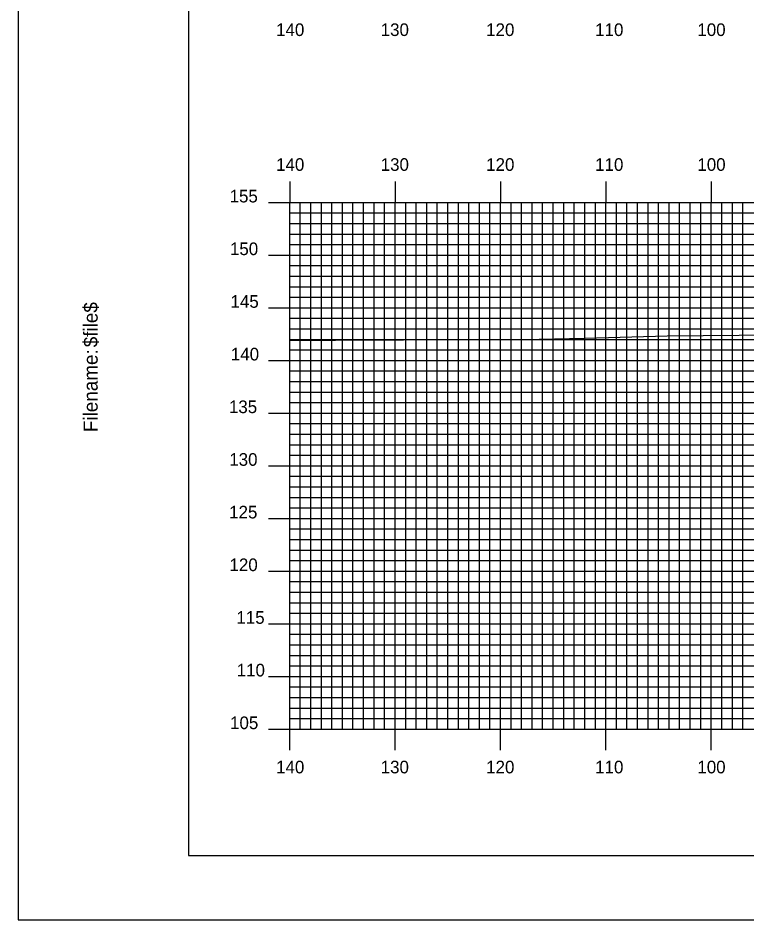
# Model space of a CAD drawing. Extents: x 1769268 to 1769611, y 442591 to 442811.
# Drawn here: x 1769267.7 to 1769336.9, y 442590.5 to 442676.2 of the extents above; entities that cross this region are included whole.
import ezdxf

# ---------------------------------------------------------------- set-up
doc = ezdxf.new("R2010")
doc.units = 0
for name, color, linetype in [('BORDER', 7, 'Continuous'), ('H_V ANNOTATION', 7, 'Continuous'), ('MAJOR', 7, 'Continuous'), ('MINOR', 7, 'Continuous'), ('PLOT BOUNDARY', 7, 'Continuous'), ('S_Roadway_Centerline', 7, 'Continuous')]:
    doc.layers.add(name, color=color, linetype=linetype)

msp = doc.modelspace()

# ---------------------------------------------------------------- linework, layer by layer
at = {"layer": 'BORDER'}
msp.add_lwpolyline([(1769283.902, 442596.665), (1769603.902, 442596.665), (1769603.902, 442806.665), (1769283.902, 442806.665)], close=True, dxfattribs=at)
at = {"layer": 'MAJOR'}
for p, q in [((1769293.502, 442660.669), (1769293.502, 442658.665)), ((1769303.502, 442660.669), (1769303.502, 442658.665)), ((1769313.502, 442660.669), (1769313.502, 442658.665)), ((1769323.502, 442660.669), (1769323.502, 442658.665)), ((1769333.502, 442660.669), (1769333.502, 442658.665)), ((1769291.498, 442658.665), (1769293.502, 442658.665)), ((1769293.502, 442658.665), (1769573.502, 442658.665)), ((1769293.502, 442608.665), (1769293.502, 442658.665)), ((1769293.502, 442608.665), (1769293.502, 442658.665)), ((1769293.502, 442658.665), (1769573.502, 442658.665)), ((1769303.502, 442608.665), (1769303.502, 442658.665)), ((1769313.502, 442608.665), (1769313.502, 442658.665)), ((1769323.502, 442608.665), (1769323.502, 442658.665)), ((1769333.502, 442608.665), (1769333.502, 442658.665)), ((1769291.498, 442653.665), (1769293.502, 442653.665)), ((1769293.502, 442653.665), (1769573.502, 442653.665)), ((1769291.498, 442648.665), (1769293.502, 442648.665)), ((1769293.502, 442648.665), (1769573.502, 442648.665)), ((1769291.498, 442643.665), (1769293.502, 442643.665)), ((1769293.502, 442643.665), (1769573.502, 442643.665)), ((1769291.498, 442638.665), (1769293.502, 442638.665)), ((1769293.502, 442638.665), (1769573.502, 442638.665)), ((1769291.498, 442633.665), (1769293.502, 442633.665)), ((1769293.502, 442633.665), (1769573.502, 442633.665)), ((1769291.498, 442628.665), (1769293.502, 442628.665)), ((1769293.502, 442628.665), (1769573.502, 442628.665)), ((1769291.498, 442623.665), (1769293.502, 442623.665)), ((1769293.502, 442623.665), (1769573.502, 442623.665)), ((1769291.498, 442618.665), (1769293.502, 442618.665)), ((1769293.502, 442618.665), (1769573.502, 442618.665)), ((1769291.498, 442613.665), (1769293.502, 442613.665)), ((1769293.502, 442613.665), (1769573.502, 442613.665)), ((1769291.498, 442608.665), (1769293.502, 442608.665)), ((1769293.502, 442608.665), (1769573.502, 442608.665)), ((1769293.502, 442608.665), (1769573.502, 442608.665)), ((1769293.502, 442606.661), (1769293.502, 442608.665)), ((1769303.502, 442606.661), (1769303.502, 442608.665)), ((1769313.502, 442606.661), (1769313.502, 442608.665)), ((1769323.502, 442606.661), (1769323.502, 442608.665)), ((1769333.502, 442606.661), (1769333.502, 442608.665))]:
    msp.add_line(p, q, dxfattribs=at)
at = {"layer": 'MINOR'}
for p, q in [((1769294.502, 442608.665), (1769294.502, 442658.665)), ((1769295.502, 442608.665), (1769295.502, 442658.665)), ((1769296.502, 442608.665), (1769296.502, 442658.665)), ((1769297.502, 442608.665), (1769297.502, 442658.665)), ((1769298.502, 442608.665), (1769298.502, 442658.665)), ((1769299.502, 442608.665), (1769299.502, 442658.665)), ((1769300.502, 442608.665), (1769300.502, 442658.665)), ((1769301.502, 442608.665), (1769301.502, 442658.665)), ((1769302.502, 442608.665), (1769302.502, 442658.665)), ((1769304.502, 442608.665), (1769304.502, 442658.665)), ((1769305.502, 442608.665), (1769305.502, 442658.665)), ((1769306.502, 442608.665), (1769306.502, 442658.665)), ((1769307.502, 442608.665), (1769307.502, 442658.665)), ((1769308.502, 442608.665), (1769308.502, 442658.665)), ((1769309.502, 442608.665), (1769309.502, 442658.665)), ((1769310.502, 442608.665), (1769310.502, 442658.665)), ((1769311.502, 442608.665), (1769311.502, 442658.665)), ((1769312.502, 442608.665), (1769312.502, 442658.665)), ((1769314.502, 442608.665), (1769314.502, 442658.665)), ((1769315.502, 442608.665), (1769315.502, 442658.665)), ((1769316.502, 442608.665), (1769316.502, 442658.665)), ((1769317.502, 442608.665), (1769317.502, 442658.665)), ((1769318.502, 442608.665), (1769318.502, 442658.665)), ((1769319.502, 442608.665), (1769319.502, 442658.665)), ((1769320.502, 442608.665), (1769320.502, 442658.665)), ((1769321.502, 442608.665), (1769321.502, 442658.665)), ((1769322.502, 442608.665), (1769322.502, 442658.665)), ((1769324.502, 442608.665), (1769324.502, 442658.665)), ((1769325.502, 442608.665), (1769325.502, 442658.665)), ((1769326.502, 442608.665), (1769326.502, 442658.665)), ((1769327.502, 442608.665), (1769327.502, 442658.665)), ((1769328.502, 442608.665), (1769328.502, 442658.665)), ((1769329.502, 442608.665), (1769329.502, 442658.665)), ((1769330.502, 442608.665), (1769330.502, 442658.665)), ((1769331.502, 442608.665), (1769331.502, 442658.665)), ((1769332.502, 442608.665), (1769332.502, 442658.665)), ((1769334.502, 442608.665), (1769334.502, 442658.665)), ((1769335.502, 442608.665), (1769335.502, 442658.665)), ((1769336.502, 442608.665), (1769336.502, 442658.665)), ((1769293.502, 442657.665), (1769573.502, 442657.665)), ((1769293.502, 442657.665), (1769295.506, 442657.665)), ((1769293.502, 442656.665), (1769573.502, 442656.665)), ((1769293.502, 442656.665), (1769295.506, 442656.665)), ((1769293.502, 442655.665), (1769573.502, 442655.665)), ((1769293.502, 442655.665), (1769295.506, 442655.665)), ((1769293.502, 442654.665), (1769573.502, 442654.665)), ((1769293.502, 442654.665), (1769295.506, 442654.665)), ((1769293.502, 442652.665), (1769573.502, 442652.665)), ((1769293.502, 442652.665), (1769295.506, 442652.665)), ((1769293.502, 442651.665), (1769573.502, 442651.665)), ((1769293.502, 442651.665), (1769295.506, 442651.665)), ((1769293.502, 442650.665), (1769573.502, 442650.665)), ((1769293.502, 442650.665), (1769295.506, 442650.665)), ((1769293.502, 442649.665), (1769573.502, 442649.665)), ((1769293.502, 442649.665), (1769295.506, 442649.665)), ((1769293.502, 442647.665), (1769573.502, 442647.665)), ((1769293.502, 442647.665), (1769295.506, 442647.665)), ((1769293.502, 442646.665), (1769573.502, 442646.665)), ((1769293.502, 442646.665), (1769295.506, 442646.665)), ((1769293.502, 442645.665), (1769573.502, 442645.665)), ((1769293.502, 442645.665), (1769295.506, 442645.665)), ((1769293.502, 442644.665), (1769573.502, 442644.665)), ((1769293.502, 442644.665), (1769295.506, 442644.665)), ((1769293.502, 442642.665), (1769573.502, 442642.665)), ((1769293.502, 442642.665), (1769295.506, 442642.665)), ((1769293.502, 442641.665), (1769573.502, 442641.665)), ((1769293.502, 442641.665), (1769295.506, 442641.665)), ((1769293.502, 442640.665), (1769573.502, 442640.665)), ((1769293.502, 442640.665), (1769295.506, 442640.665)), ((1769293.502, 442639.665), (1769573.502, 442639.665)), ((1769293.502, 442639.665), (1769295.506, 442639.665)), ((1769293.502, 442637.665), (1769573.502, 442637.665)), ((1769293.502, 442637.665), (1769295.506, 442637.665)), ((1769293.502, 442636.665), (1769573.502, 442636.665)), ((1769293.502, 442636.665), (1769295.506, 442636.665)), ((1769293.502, 442635.665), (1769573.502, 442635.665)), ((1769293.502, 442635.665), (1769295.506, 442635.665)), ((1769293.502, 442634.665), (1769573.502, 442634.665)), ((1769293.502, 442634.665), (1769295.506, 442634.665)), ((1769293.502, 442632.665), (1769573.502, 442632.665)), ((1769293.502, 442632.665), (1769295.506, 442632.665)), ((1769293.502, 442631.665), (1769573.502, 442631.665)), ((1769293.502, 442631.665), (1769295.506, 442631.665)), ((1769293.502, 442630.665), (1769573.502, 442630.665)), ((1769293.502, 442630.665), (1769295.506, 442630.665)), ((1769293.502, 442629.665), (1769573.502, 442629.665)), ((1769293.502, 442629.665), (1769295.506, 442629.665)), ((1769293.502, 442627.665), (1769573.502, 442627.665)), ((1769293.502, 442627.665), (1769295.506, 442627.665)), ((1769293.502, 442626.665), (1769573.502, 442626.665)), ((1769293.502, 442626.665), (1769295.506, 442626.665)), ((1769293.502, 442625.665), (1769573.502, 442625.665)), ((1769293.502, 442625.665), (1769295.506, 442625.665)), ((1769293.502, 442624.665), (1769573.502, 442624.665)), ((1769293.502, 442624.665), (1769295.506, 442624.665)), ((1769293.502, 442622.665), (1769573.502, 442622.665)), ((1769293.502, 442622.665), (1769295.506, 442622.665)), ((1769293.502, 442621.665), (1769573.502, 442621.665)), ((1769293.502, 442621.665), (1769295.506, 442621.665)), ((1769293.502, 442620.665), (1769573.502, 442620.665)), ((1769293.502, 442620.665), (1769295.506, 442620.665)), ((1769293.502, 442619.665), (1769573.502, 442619.665)), ((1769293.502, 442619.665), (1769295.506, 442619.665)), ((1769293.502, 442617.665), (1769573.502, 442617.665)), ((1769293.502, 442617.665), (1769295.506, 442617.665)), ((1769293.502, 442616.665), (1769573.502, 442616.665)), ((1769293.502, 442616.665), (1769295.506, 442616.665)), ((1769293.502, 442615.665), (1769573.502, 442615.665)), ((1769293.502, 442615.665), (1769295.506, 442615.665)), ((1769293.502, 442614.665), (1769573.502, 442614.665)), ((1769293.502, 442614.665), (1769295.506, 442614.665)), ((1769293.502, 442612.665), (1769573.502, 442612.665)), ((1769293.502, 442612.665), (1769295.506, 442612.665)), ((1769293.502, 442611.665), (1769573.502, 442611.665)), ((1769293.502, 442611.665), (1769295.506, 442611.665)), ((1769293.502, 442610.665), (1769573.502, 442610.665)), ((1769293.502, 442610.665), (1769295.506, 442610.665)), ((1769293.502, 442609.665), (1769573.502, 442609.665)), ((1769293.502, 442609.665), (1769295.506, 442609.665))]:
    msp.add_line(p, q, dxfattribs=at)
at = {"layer": 'PLOT BOUNDARY'}
msp.add_lwpolyline([(1769267.715, 442590.547), (1769607.715, 442590.547), (1769607.715, 442810.547), (1769267.715, 442810.547)], close=True, dxfattribs=at)
at = {"layer": 'S_Roadway_Centerline'}
msp.add_lwpolyline([(1769293.502, 442645.582), (1769297.626, 442645.603), (1769297.746, 442645.603), (1769297.777, 442645.603), (1769297.83, 442645.603), (1769317.17, 442645.685), (1769321.501, 442645.781), (1769329.322, 442646.007), (1769336.146, 442646.051), (1769346.231, 442646.246)], dxfattribs=at)

# ---------------------------------------------------------------- texts
at = {"layer": 'BORDER'}
for s, p in [('$file$', (1769275.272, 442644.916)), ('Filename:', (1769275.272, 442636.862))]:
    msp.add_text(s, height=1.3392, rotation=90, dxfattribs=at).set_placement(p)
at = {"layer": 'H_V ANNOTATION'}
for s, p in [('140', (1769292.207, 442674.465)), ('130', (1769302.132, 442674.465)), ('120', (1769312.142, 442674.465)), ('110', (1769322.485, 442674.465)), ('100', (1769332.185, 442674.465)), ('140', (1769292.207, 442661.665)), ('130', (1769302.132, 442661.665)), ('120', (1769312.142, 442661.665)), ('110', (1769322.485, 442661.665)), ('100', (1769332.185, 442661.665)), ('155', (1769287.794, 442658.665)), ('150', (1769287.826, 442653.665)), ('145', (1769287.88, 442648.665)), ('140', (1769287.912, 442643.665)), ('135', (1769287.73, 442638.665)), ('130', (1769287.762, 442633.665)), ('125', (1769287.751, 442628.665)), ('120', (1769287.783, 442623.665)), ('115', (1769288.436, 442618.665)), ('110', (1769288.468, 442613.665)), ('105', (1769287.837, 442608.665)), ('140', (1769292.207, 442604.465)), ('130', (1769302.132, 442604.465)), ('120', (1769312.142, 442604.465)), ('110', (1769322.485, 442604.465)), ('100', (1769332.185, 442604.465))]:
    msp.add_text(s, height=1.2, dxfattribs=at).set_placement(p)
at = {"layer": 'MAJOR'}
msp.add_text('-', height=0.012, dxfattribs=at).set_placement((1769293.493, 442608.665))

doc.saveas('drawing.dxf')
